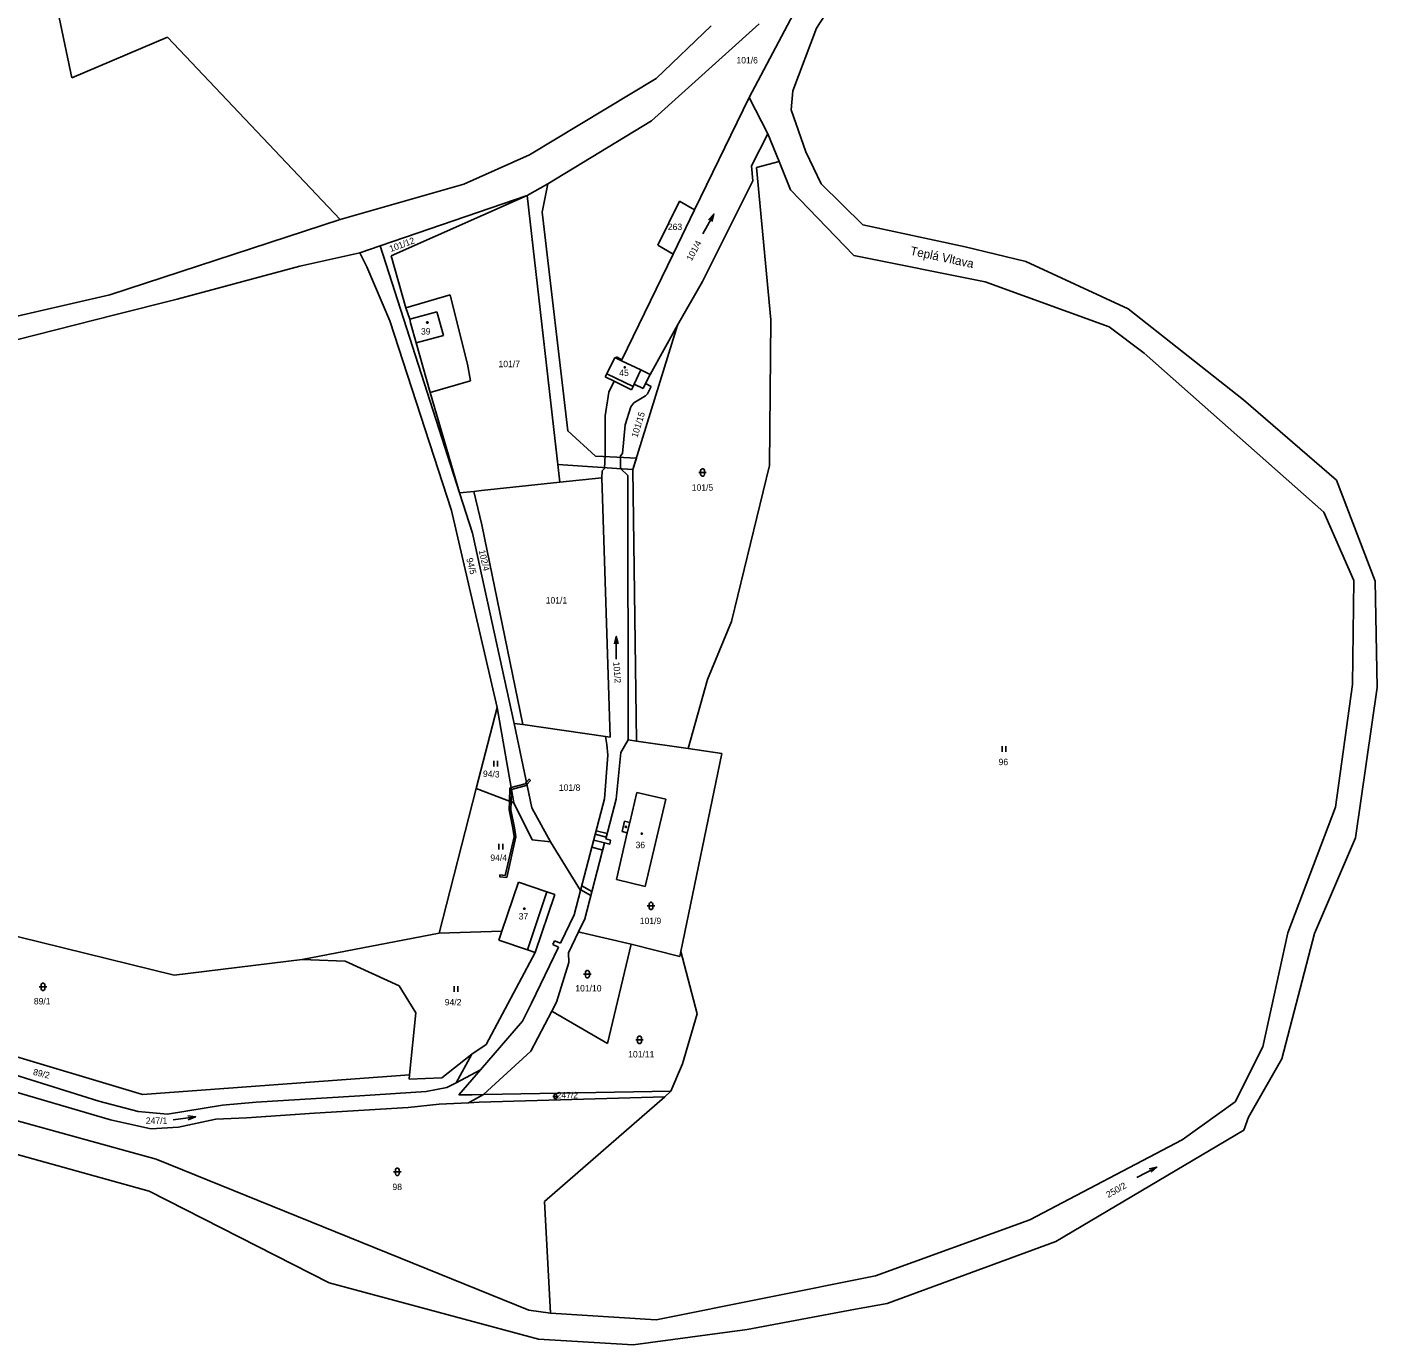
# Model space of a CAD drawing. Extents: x -811039 to -805820, y -1161436 to -1155864.
# Drawn here: x -809389.3 to -809031.3, y -1160723.7 to -1160374.2 of the extents above; entities that cross this region are included whole.
import ezdxf

# ---------------------------------------------------------------- set-up
doc = ezdxf.new("R2010")
doc.units = 0
for name, color, linetype in [('Default', 7, 'Continuous'), ('Hranice kat_území', 7, 'Continuous'), ('Hranice parcel', 7, 'Continuous'), ('Parcelní čísla', 7, 'Continuous'), ('Pop  PČ popisy', 7, 'Continuous'), ('Vnitřní kresba', 7, 'Continuous'), ('Věcná břemena k části', 7, 'Continuous'), ('Značky budov', 7, 'Continuous'), ('Značky kultur', 7, 'Continuous')]:
    doc.layers.add(name, color=color, linetype=linetype)

# ---------------------------------------------------------------- blocks, each defined once
blk = doc.blocks.new('306')
at = {"layer": 'Default'}
for p, q in [((-0.5, 1.5), (-0.5, 0)), ((0.5, 0), (0.5, 1.5))]:
    blk.add_line(p, q, dxfattribs=at)
blk = doc.blocks.new('316')
at = {"layer": 'Default'}
for points in [[(-1, 1), (0.27, 1), (1, 1)], [(-0.5, 1.5), (-0.4, 1.79), (-0.15, 1.97), (0.16, 1.97), (0.41, 1.79), (0.51, 1.5), (0.51, 0.5), (0.41, 0.21), (0.16, 0.03), (-0.15, 0.03), (-0.4, 0.21), (-0.5, 0.5), (-0.5, 1.5)]]:
    blk.add_lwpolyline(points, dxfattribs=at)
blk = doc.blocks.new('802')
at = {"layer": 'Default'}
blk.add_line((-3, 0), (3, 0), dxfattribs=at)
blk.add_lwpolyline([(1, 0.5), (3, 0), (1, -0.5)], dxfattribs=at)
blk = doc.blocks.new('402')
at = {"layer": 'Default'}
blk.add_lwpolyline([(0.09, 0.15), (0.18, 0), (0.09, -0.15), (-0.09, -0.15), (-0.18, 0), (-0.09, 0.15), (0.09, 0.15)], dxfattribs=at)

msp = doc.modelspace()

# ---------------------------------------------------------------- linework, layer by layer
at = {"layer": 'Hranice kat_území'}
for p, q in [((-809164.76, -1160350.97), (-809179.95, -1160374.5)), ((-809179.95, -1160374.5), (-809186.23, -1160391.12)), ((-809186.23, -1160391.12), (-809186.68, -1160396.21)), ((-809186.68, -1160396.21), (-809182.8, -1160407.28)), ((-809182.8, -1160407.28), (-809178.72, -1160415.77)), ((-809178.72, -1160415.77), (-809167.64, -1160426.68)), ((-809167.64, -1160426.68), (-809140.49, -1160432.53)), ((-809140.49, -1160432.53), (-809124.41, -1160436.38)), ((-809124.41, -1160436.38), (-809097.26, -1160448.94)), ((-809097.26, -1160448.94), (-809066.71, -1160473.11)), ((-809066.71, -1160473.11), (-809042.09, -1160494.36)), ((-809042.09, -1160494.36), (-809031.85, -1160521.14)), ((-809031.85, -1160521.14), (-809031.32, -1160549.36)), ((-809031.32, -1160549.36), (-809037.05, -1160589.21)), ((-809037.05, -1160589.21), (-809047.93, -1160614.55)), ((-809047.93, -1160614.55), (-809056.59, -1160647.8)), ((-809056.59, -1160647.8), (-809065.39, -1160663.28)), ((-809065.39, -1160663.28), (-809066.66, -1160666.68)), ((-809356.9, -1160682.85), (-809407.74, -1160668.76)), ((-809066.66, -1160666.68), (-809116.5, -1160696.21)), ((-809309.13, -1160707.2), (-809356.9, -1160682.85)), ((-809116.5, -1160696.21), (-809161.22, -1160712.64)), ((-809253.61, -1160722.14), (-809309.13, -1160707.2)), ((-809161.22, -1160712.64), (-809169.64, -1160714.18)), ((-809169.64, -1160714.18), (-809198.33, -1160719.6)), ((-809198.33, -1160719.6), (-809228.56, -1160723.67)), ((-809228.56, -1160723.67), (-809253.61, -1160722.14))]:
    msp.add_line(p, q, dxfattribs=at)
at = {"layer": 'Hranice parcel'}
for p, q in [((-809377.38, -1160387.67), (-809383.16, -1160360.13)), ((-809184.55, -1160367.86), (-809197.83, -1160392.88)), ((-809195.12, -1160373.34), (-809223.69, -1160399.1)), ((-809222.46, -1160387.84), (-809207.83, -1160373.93)), ((-809351.99, -1160376.94), (-809377.38, -1160387.67)), ((-809306.27, -1160425.24), (-809351.99, -1160376.94)), ((-809256.07, -1160408.12), (-809222.46, -1160387.84)), ((-809212.26, -1160422.67), (-809197.83, -1160392.88)), ((-809192.83, -1160402.55), (-809197.83, -1160392.88)), ((-809251.15, -1160415.81), (-809223.69, -1160399.1)), ((-809197.18, -1160411.03), (-809192.83, -1160402.55)), ((-809192.83, -1160402.55), (-809189.85, -1160409.88)), ((-809273.45, -1160415.91), (-809256.07, -1160408.12)), ((-809197.18, -1160411.03), (-809196.81, -1160415.03)), ((-809195.89, -1160411.46), (-809189.85, -1160409.88)), ((-809195.89, -1160411.46), (-809192.04, -1160451.84)), ((-809189.85, -1160409.88), (-809186.79, -1160417.41)), ((-809196.81, -1160415.03), (-809210.16, -1160441.71)), ((-809306.27, -1160425.24), (-809273.45, -1160415.91)), ((-809295.6, -1160432.22), (-809256.63, -1160418.86)), ((-809256.63, -1160418.86), (-809292.68, -1160434.92)), ((-809256.63, -1160418.86), (-809251.15, -1160415.81)), ((-809256.63, -1160418.86), (-809247.98, -1160494.88)), ((-809186.79, -1160417.41), (-809170.07, -1160434.82)), ((-809216.3, -1160420.4), (-809222.04, -1160432.05)), ((-809217.95, -1160434.43), (-809212.26, -1160422.67)), ((-809212.26, -1160422.67), (-809216.3, -1160420.4)), ((-809367.32, -1160445.21), (-809306.27, -1160425.24)), ((-809295.6, -1160432.22), (-809300.99, -1160434.07)), ((-809295.6, -1160432.22), (-809274.57, -1160497.77)), ((-809222.04, -1160432.05), (-809217.95, -1160434.43)), ((-809300.99, -1160434.07), (-809316.98, -1160437.61)), ((-809299.17, -1160437.78), (-809300.99, -1160434.07)), ((-809292.68, -1160434.92), (-809288.8, -1160448.68)), ((-809231.52, -1160462.45), (-809217.95, -1160434.43)), ((-809170.07, -1160434.82), (-809135.23, -1160441.78)), ((-809316.98, -1160437.61), (-809349.42, -1160446.41)), ((-809293.09, -1160452.12), (-809299.17, -1160437.78)), ((-809216.77, -1160453.3), (-809210.16, -1160441.71)), ((-809135.23, -1160441.78), (-809102.35, -1160453.7)), ((-809465.78, -1160467.81), (-809367.32, -1160445.21)), ((-809349.42, -1160446.41), (-809365.99, -1160450.5)), ((-809288.8, -1160448.68), (-809277.04, -1160445.26)), ((-809274.34, -1160456.26), (-809277.04, -1160445.26)), ((-809365.99, -1160450.5), (-809425.11, -1160465.49)), ((-809287.79, -1160451.7), (-809288.8, -1160448.68)), ((-809276.73, -1160502.4), (-809293.09, -1160452.12)), ((-809287.58, -1160452.66), (-809287.79, -1160451.7)), ((-809286.1, -1160457.99), (-809287.58, -1160452.66)), ((-809216.77, -1160453.3), (-809228.62, -1160491.56)), ((-809216.77, -1160453.3), (-809224.08, -1160466.33)), ((-809192.43, -1160490.44), (-809192.04, -1160451.84)), ((-809102.35, -1160453.7), (-809093.02, -1160460.66)), ((-809282.38, -1160471.12), (-809286.1, -1160457.99)), ((-809272.49, -1160463.6), (-809274.34, -1160456.26)), ((-809233.42, -1160461.84), (-809235.54, -1160466.17)), ((-809233.1, -1160462.01), (-809233.42, -1160461.84)), ((-809232.94, -1160461.69), (-809233.1, -1160462.01)), ((-809231.52, -1160462.45), (-809232.94, -1160461.69)), ((-809093.02, -1160460.66), (-809045.41, -1160502.89)), ((-809272.49, -1160463.6), (-809271.65, -1160468.06)), ((-809231.64, -1160462.71), (-809231.52, -1160462.45)), ((-809226.56, -1160465.13), (-809231.64, -1160462.71)), ((-809224.08, -1160466.33), (-809226.56, -1160465.13)), ((-809271.65, -1160468.06), (-809282.38, -1160471.12)), ((-809235.54, -1160466.17), (-809235.94, -1160466.99)), ((-809233.56, -1160468.15), (-809235.94, -1160466.99)), ((-809233.56, -1160468.15), (-809235.03, -1160471.04)), ((-809228.95, -1160470.38), (-809233.56, -1160468.15)), ((-809228.3, -1160468.95), (-809228.57, -1160469.54)), ((-809228.3, -1160468.95), (-809225.86, -1160470.08)), ((-809225.24, -1160468.77), (-809225.86, -1160470.08)), ((-809225.24, -1160468.77), (-809224.08, -1160466.33)), ((-809223.8, -1160469.49), (-809225.24, -1160468.77)), ((-809282.38, -1160471.12), (-809274.57, -1160497.77)), ((-809235.03, -1160471.04), (-809235.97, -1160477.33)), ((-809228.95, -1160470.38), (-809228.57, -1160469.54)), ((-809228.36, -1160473.9), (-809225.26, -1160472.02)), ((-809225.26, -1160472.02), (-809224.79, -1160471.45)), ((-809224.79, -1160471.45), (-809223.8, -1160469.49)), ((-809230.64, -1160479.68), (-809229.19, -1160474.88)), ((-809229.19, -1160474.88), (-809228.36, -1160473.9)), ((-809235.97, -1160477.33), (-809235.99, -1160487.61)), ((-809231.37, -1160487.29), (-809230.64, -1160479.68)), ((-809235.99, -1160487.61), (-809236.18, -1160491.27)), ((-809231.87, -1160487.96), (-809231.37, -1160487.29)), ((-809231.87, -1160491.31), (-809231.87, -1160487.96)), ((-809202.48, -1160531.86), (-809192.43, -1160490.44)), ((-809247.98, -1160494.88), (-809236.84, -1160493.73)), ((-809236.73, -1160491.87), (-809236.84, -1160493.73)), ((-809234.66, -1160562.53), (-809236.84, -1160493.73)), ((-809236.18, -1160491.27), (-809236.73, -1160491.87)), ((-809229.98, -1160493.13), (-809231.87, -1160491.31)), ((-809229.89, -1160563.22), (-809229.98, -1160493.13)), ((-809228.62, -1160491.56), (-809227.7, -1160563.54)), ((-809274.57, -1160497.77), (-809270.81, -1160497.36)), ((-809271.16, -1160508.39), (-809274.57, -1160497.77)), ((-809270.81, -1160497.36), (-809268.77, -1160497.15)), ((-809270.81, -1160497.36), (-809268.69, -1160506.23)), ((-809268.77, -1160497.15), (-809247.98, -1160494.88)), ((-809276.73, -1160502.4), (-809264.63, -1160554.6)), ((-809045.41, -1160502.89), (-809037.46, -1160521.01)), ((-809260.11, -1160558.85), (-809271.16, -1160508.39)), ((-809268.69, -1160506.23), (-809257.78, -1160559.19)), ((-809037.46, -1160521.01), (-809037.85, -1160548.51)), ((-809208.82, -1160547.21), (-809202.48, -1160531.86)), ((-809208.82, -1160547.21), (-809213.95, -1160565.53)), ((-809037.85, -1160548.51), (-809042.35, -1160581.08)), ((-809270.17, -1160576.15), (-809264.63, -1160554.6)), ((-809264.63, -1160554.6), (-809260.21, -1160579.92)), ((-809257.78, -1160559.19), (-809260.11, -1160558.85)), ((-809255.41, -1160581.27), (-809260.11, -1160558.85)), ((-809235.85, -1160562.36), (-809257.78, -1160559.19)), ((-809235.49, -1160564.42), (-809235.85, -1160562.36)), ((-809234.66, -1160562.53), (-809235.85, -1160562.36)), ((-809235.26, -1160567.28), (-809235.49, -1160564.42)), ((-809231.78, -1160566.6), (-809230.88, -1160564.92)), ((-809230.88, -1160564.92), (-809229.89, -1160563.22)), ((-809227.7, -1160563.54), (-809229.89, -1160563.22)), ((-809227.7, -1160563.54), (-809213.95, -1160565.53)), ((-809205.04, -1160566.82), (-809213.95, -1160565.53)), ((-809236.18, -1160578.84), (-809235.26, -1160567.28)), ((-809233.1, -1160578.94), (-809231.78, -1160566.6)), ((-809215.93, -1160619.31), (-809205.04, -1160566.82)), ((-809270.17, -1160576.15), (-809279.97, -1160614.5)), ((-809260.21, -1160579.92), (-809270.17, -1160576.15)), ((-809260.21, -1160579.92), (-809255.3, -1160589.69)), ((-809239.51, -1160591.67), (-809236.18, -1160578.84)), ((-809235.8, -1160589.46), (-809233.1, -1160578.94)), ((-809229.45, -1160585.13), (-809227.55, -1160577.2)), ((-809219.93, -1160578.96), (-809227.55, -1160577.2)), ((-809225.36, -1160602.11), (-809219.93, -1160578.96)), ((-809250.46, -1160590.27), (-809255.41, -1160581.27)), ((-809042.35, -1160581.08), (-809054.99, -1160614.43)), ((-809231.46, -1160587.51), (-809230.84, -1160584.8)), ((-809230.84, -1160584.8), (-809229.45, -1160585.13)), ((-809255.3, -1160589.69), (-809250.46, -1160590.27)), ((-809242.5, -1160603.16), (-809250.46, -1160590.27)), ((-809241.37, -1160610.65), (-809236.11, -1160590.56)), ((-809236.11, -1160590.56), (-809234.78, -1160590.84)), ((-809234.57, -1160589.8), (-809235.8, -1160589.46)), ((-809234.57, -1160589.8), (-809234.78, -1160590.84)), ((-809233.01, -1160600.23), (-809230.14, -1160587.85)), ((-809230.14, -1160587.85), (-809231.46, -1160587.51)), ((-809487.54, -1160591.74), (-809350.28, -1160625.64)), ((-809242.5, -1160603.16), (-809239.51, -1160591.67)), ((-809258.95, -1160600.98), (-809263.36, -1160613.99)), ((-809258.95, -1160600.98), (-809251.44, -1160603.51)), ((-809225.36, -1160602.11), (-809233.01, -1160600.23)), ((-809249.34, -1160604.22), (-809254.57, -1160619.56)), ((-809251.44, -1160603.51), (-809249.34, -1160604.22)), ((-809244.16, -1160609.58), (-809242.5, -1160603.16)), ((-809244.16, -1160609.58), (-809247.83, -1160617.15)), ((-809243.05, -1160614.15), (-809241.37, -1160610.65)), ((-809279.97, -1160614.5), (-809316.34, -1160621.46)), ((-809279.97, -1160614.5), (-809263.36, -1160613.99)), ((-809263.36, -1160613.99), (-809264.15, -1160616.33)), ((-809245.7, -1160619.71), (-809243.05, -1160614.15)), ((-809243.05, -1160614.15), (-809242.41, -1160614.3)), ((-809229.08, -1160617.4), (-809242.41, -1160614.3)), ((-809054.99, -1160614.43), (-809061.55, -1160644.59)), ((-809254.57, -1160619.56), (-809267.5, -1160643.96)), ((-809256.58, -1160618.86), (-809264.15, -1160616.33)), ((-809254.57, -1160619.56), (-809256.58, -1160618.86)), ((-809248.33, -1160618.18), (-809255.54, -1160633.04)), ((-809249.41, -1160616.47), (-809249.81, -1160617.46)), ((-809249.81, -1160617.46), (-809248.33, -1160618.18)), ((-809247.83, -1160617.15), (-809249.41, -1160616.47)), ((-809229.08, -1160617.4), (-809235.39, -1160643.76)), ((-809229.08, -1160617.4), (-809216.2, -1160620.63)), ((-809216.2, -1160620.63), (-809215.93, -1160619.31)), ((-809211.6, -1160635.88), (-809215.93, -1160619.31)), ((-809350.28, -1160625.64), (-809316.34, -1160621.46)), ((-809316.34, -1160621.46), (-809304.92, -1160621.91)), ((-809304.92, -1160621.91), (-809290.62, -1160628.47)), ((-809248.88, -1160632.81), (-809245.62, -1160622.23)), ((-809245.62, -1160622.23), (-809245.7, -1160619.71)), ((-809290.62, -1160628.47), (-809286.17, -1160635.59)), ((-809257.88, -1160637.82), (-809255.54, -1160633.04)), ((-809250.09, -1160635.17), (-809248.88, -1160632.81)), ((-809370.26, -1160659.02), (-809442.45, -1160636.38)), ((-809358.61, -1160657.26), (-809433.66, -1160634.73)), ((-809286.17, -1160635.59), (-809287.82, -1160652.05)), ((-809255.68, -1160645.76), (-809250.09, -1160635.17)), ((-809250.09, -1160635.17), (-809235.39, -1160643.76)), ((-809215.5, -1160649.1), (-809211.6, -1160635.88)), ((-809269.06, -1160650.74), (-809257.88, -1160637.82)), ((-809271.35, -1160646.59), (-809267.5, -1160643.96)), ((-809061.55, -1160644.59), (-809068.93, -1160659.2)), ((-809421.07, -1160648.18), (-809367.17, -1160663.97)), ((-809279.31, -1160652.87), (-809271.35, -1160646.59)), ((-809271.35, -1160646.59), (-809275.51, -1160654.19)), ((-809268.28, -1160657.28), (-809255.68, -1160645.76)), ((-809269.06, -1160650.74), (-809275.51, -1160654.19)), ((-809269.06, -1160650.74), (-809274.76, -1160657.33)), ((-809218.56, -1160656.33), (-809215.5, -1160649.1)), ((-809287.82, -1160652.05), (-809358.61, -1160657.26)), ((-809287.82, -1160652.05), (-809287.92, -1160653.16)), ((-809287.92, -1160653.16), (-809279.31, -1160652.87)), ((-809277.94, -1160655.44), (-809275.51, -1160654.19)), ((-809328.48, -1160659.3), (-809301, -1160657.58)), ((-809301, -1160657.58), (-809283.43, -1160656.43)), ((-809283.43, -1160656.43), (-809277.94, -1160655.44)), ((-809274.76, -1160657.33), (-809271.25, -1160657.34)), ((-809272.24, -1160659.43), (-809268.28, -1160657.28)), ((-809271.25, -1160657.34), (-809268.28, -1160657.28)), ((-809269.37, -1160659.27), (-809220.16, -1160657.9)), ((-809268.28, -1160657.28), (-809218.56, -1160656.33)), ((-809220.16, -1160657.9), (-809252.03, -1160685.65)), ((-809220.16, -1160657.9), (-809218.56, -1160656.33)), ((-809355.04, -1160674.38), (-809407.93, -1160659.83)), ((-809370.26, -1160659.02), (-809359.81, -1160661.74)), ((-809359.81, -1160661.74), (-809352.04, -1160662.44)), ((-809352.04, -1160662.44), (-809337.45, -1160660.05)), ((-809337.45, -1160660.05), (-809328.48, -1160659.3)), ((-809331.05, -1160663.42), (-809313.05, -1160662.24)), ((-809313.05, -1160662.24), (-809288.22, -1160660.69)), ((-809288.22, -1160660.69), (-809279.96, -1160659.85)), ((-809272.24, -1160659.43), (-809279.96, -1160659.85)), ((-809269.37, -1160659.27), (-809272.24, -1160659.43)), ((-809068.93, -1160659.2), (-809082.95, -1160669.26)), ((-809367.17, -1160663.97), (-809356.44, -1160666.32)), ((-809349.13, -1160665.91), (-809356.44, -1160666.32)), ((-809339.21, -1160663.81), (-809349.13, -1160665.91)), ((-809331.05, -1160663.42), (-809339.21, -1160663.81)), ((-809082.95, -1160669.26), (-809123.36, -1160690.51)), ((-809256.22, -1160714.42), (-809355.04, -1160674.38)), ((-809252.03, -1160685.65), (-809250.49, -1160715.26)), ((-809123.36, -1160690.51), (-809164.31, -1160705.3)), ((-809164.31, -1160705.3), (-809222.45, -1160717.01)), ((-809250.49, -1160715.26), (-809256.22, -1160714.42)), ((-809222.45, -1160717.01), (-809250.49, -1160715.26))]:
    msp.add_line(p, q, dxfattribs=at)
at = {"layer": 'Vnitřní kresba'}
for p, q in [((-809287.79, -1160451.7), (-809280.6, -1160449.7)), ((-809280.6, -1160449.7), (-809280.34, -1160450.66)), ((-809280.34, -1160450.66), (-809278.86, -1160455.98)), ((-809278.86, -1160455.98), (-809286.1, -1160457.99)), ((-809233.1, -1160462.01), (-809231.64, -1160462.71)), ((-809226.56, -1160465.13), (-809228.3, -1160468.95)), ((-809235.54, -1160466.17), (-809228.57, -1160469.54)), ((-809230.14, -1160587.85), (-809229.45, -1160585.13)), ((-809251.44, -1160603.51), (-809256.58, -1160618.86))]:
    msp.add_line(p, q, dxfattribs=at)
at = {"layer": 'Věcná břemena k části'}
for points in [[(-809228.62, -1160491.56), (-809232.84, -1160491.27), (-809236.68, -1160491.01), (-809248.51, -1160490.2), (-809256.63, -1160418.86), (-809251.15, -1160415.81), (-809252.66, -1160423.34), (-809245.9, -1160481.32), (-809238.53, -1160487.97), (-809236.5, -1160488.08), (-809232.91, -1160488.27), (-809227.69, -1160488.56)], [(-809228.62, -1160491.56), (-809232.84, -1160491.27), (-809236.68, -1160491.01), (-809248.51, -1160490.2), (-809256.63, -1160418.86), (-809251.15, -1160415.81), (-809252.66, -1160423.34), (-809245.9, -1160481.32), (-809238.53, -1160487.97), (-809236.5, -1160488.08), (-809232.91, -1160488.27), (-809227.69, -1160488.56)], [(-809261.37, -1160579.48), (-809261.25, -1160575.99), (-809260.91, -1160575.89), (-809260.78, -1160576.67), (-809260.88, -1160579.67)], [(-809260.91, -1160575.89), (-809257.23, -1160574.85), (-809256.85, -1160574.41), (-809256.72, -1160575.03), (-809256.95, -1160575.29), (-809260.77, -1160576.37), (-809260.78, -1160576.67)], [(-809256.85, -1160574.41), (-809256.16, -1160573.63), (-809255.78, -1160573.96), (-809256.72, -1160575.03)], [(-809263.88, -1160599.03), (-809262.47, -1160599.15), (-809260.13, -1160588.94), (-809260.48, -1160586.61), (-809261.45, -1160581.79), (-809261.37, -1160579.48), (-809260.88, -1160579.67), (-809260.95, -1160581.75), (-809259.98, -1160586.53), (-809259.63, -1160588.96), (-809262.09, -1160599.69), (-809263.92, -1160599.52)], [(-809238.38, -1160587.31), (-809235.43, -1160588.03), (-809235.68, -1160589), (-809238.63, -1160588.27)], [(-809239.02, -1160589.79), (-809236.11, -1160590.56), (-809236.61, -1160592.47), (-809239.51, -1160591.67)], [(-809242.18, -1160601.95), (-809239.49, -1160603.46), (-809239.75, -1160604.46), (-809242.44, -1160602.95)]]:
    msp.add_lwpolyline(points, close=True, dxfattribs=at)

# ---------------------------------------------------------------- block references
at = {"layer": 'Značky budov'}
for p in [(-809283.13, -1160452.56), (-809230.8, -1160464.44), (-809230.48, -1160586.29), (-809226.28, -1160588.11), (-809257.41, -1160607.98)]:
    msp.add_blockref('402', p, dxfattribs=at)
at = {"layer": 'Značky kultur'}
for p, rotation in [((-809208.62, -1160426.43), 60.61893499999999), ((-809233.04, -1160538.79), 90.01166999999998), ((-809347.57, -1160663.58), 8.193296), ((-809092.35, -1160677.89), 27.96034)]:
    msp.add_blockref('802', p, dxfattribs=dict(at, rotation=rotation))
for name, p in [('316', (-809210.16, -1160493.31)), ('306', (-809130.25, -1160566.43)), ('306', (-809265.01, -1160570.26)), ('306', (-809263.64, -1160592.3)), ('316', (-809223.82, -1160608.27)), ('316', (-809240.68, -1160626.31)), ('316', (-809385.04, -1160629.71)), ('306', (-809275.53, -1160630.01)), ('316', (-809226.88, -1160643.76)), ('316', (-809291.11, -1160678.73))]:
    msp.add_blockref(name, p, dxfattribs=at)
at = {"layer": 'Značky kultur', "xscale": 0.67, "yscale": 0.67}
msp.add_blockref('316', (-809249.18, -1160658.42), dxfattribs=at)

# ---------------------------------------------------------------- texts
at = {"layer": 'Parcelní čísla'}
for s, p in [('101/6', (-809201.17, -1160383.88)), ('263', (-809219.36, -1160428.05)), ('39', (-809284.82, -1160455.76)), ('101/7', (-809264.26, -1160464.41)), ('45', (-809232.24, -1160466.76)), ('101/5', (-809213.02, -1160497.17)), ('101/1', (-809251.74, -1160527.07)), ('96', (-809131.66, -1160569.93)), ('101/8', (-809248.26, -1160576.74)), ('36', (-809227.92, -1160591.94)), ('94/4', (-809266.42, -1160595.32)), ('37', (-809258.9, -1160610.85)), ('101/9', (-809226.8, -1160612.07)), ('101/10', (-809243.89, -1160629.94)), ('89/1', (-809387.46, -1160633.37)), ('94/2', (-809278.51, -1160633.63)), ('101/11', (-809229.88, -1160647.44)), ('247/2', (-809248.85, -1160658.26)), ('247/1', (-809357.77, -1160665.04)), ('98', (-809292.38, -1160682.59))]:
    msp.add_text(s, height=1.7, dxfattribs=at).set_placement(p)
for s, rotation, p in [('101/12', 20.168, (-809292.84, -1160433.9)), ('101/4', 61.536, (-809213.06, -1160436.4)), ('101/15', 72.766, (-809227.45, -1160483.22)), ('94/5', 284.474, (-809272.8, -1160515.23)), ('102/4', 283.098, (-809269.51, -1160513.06)), ('101/2', 274.218, (-809233.84, -1160542.58)), ('94/3', 357.526, (-809268.42, -1160573.03)), ('89/2', 346.124, (-809387.79, -1160652.01)), ('250/2', 29.278, (-809102.55, -1160684.7))]:
    msp.add_text(s, height=1.7, rotation=rotation, dxfattribs=at).set_placement(p)
at = {"layer": 'Pop  PČ popisy'}
msp.add_text('Teplá Vltava', height=2.3, rotation=347.957, dxfattribs=at).set_placement((-809155.23, -1160434.59))

doc.saveas('drawing.dxf')
